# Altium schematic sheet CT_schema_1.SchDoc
size 470 x 459 mm
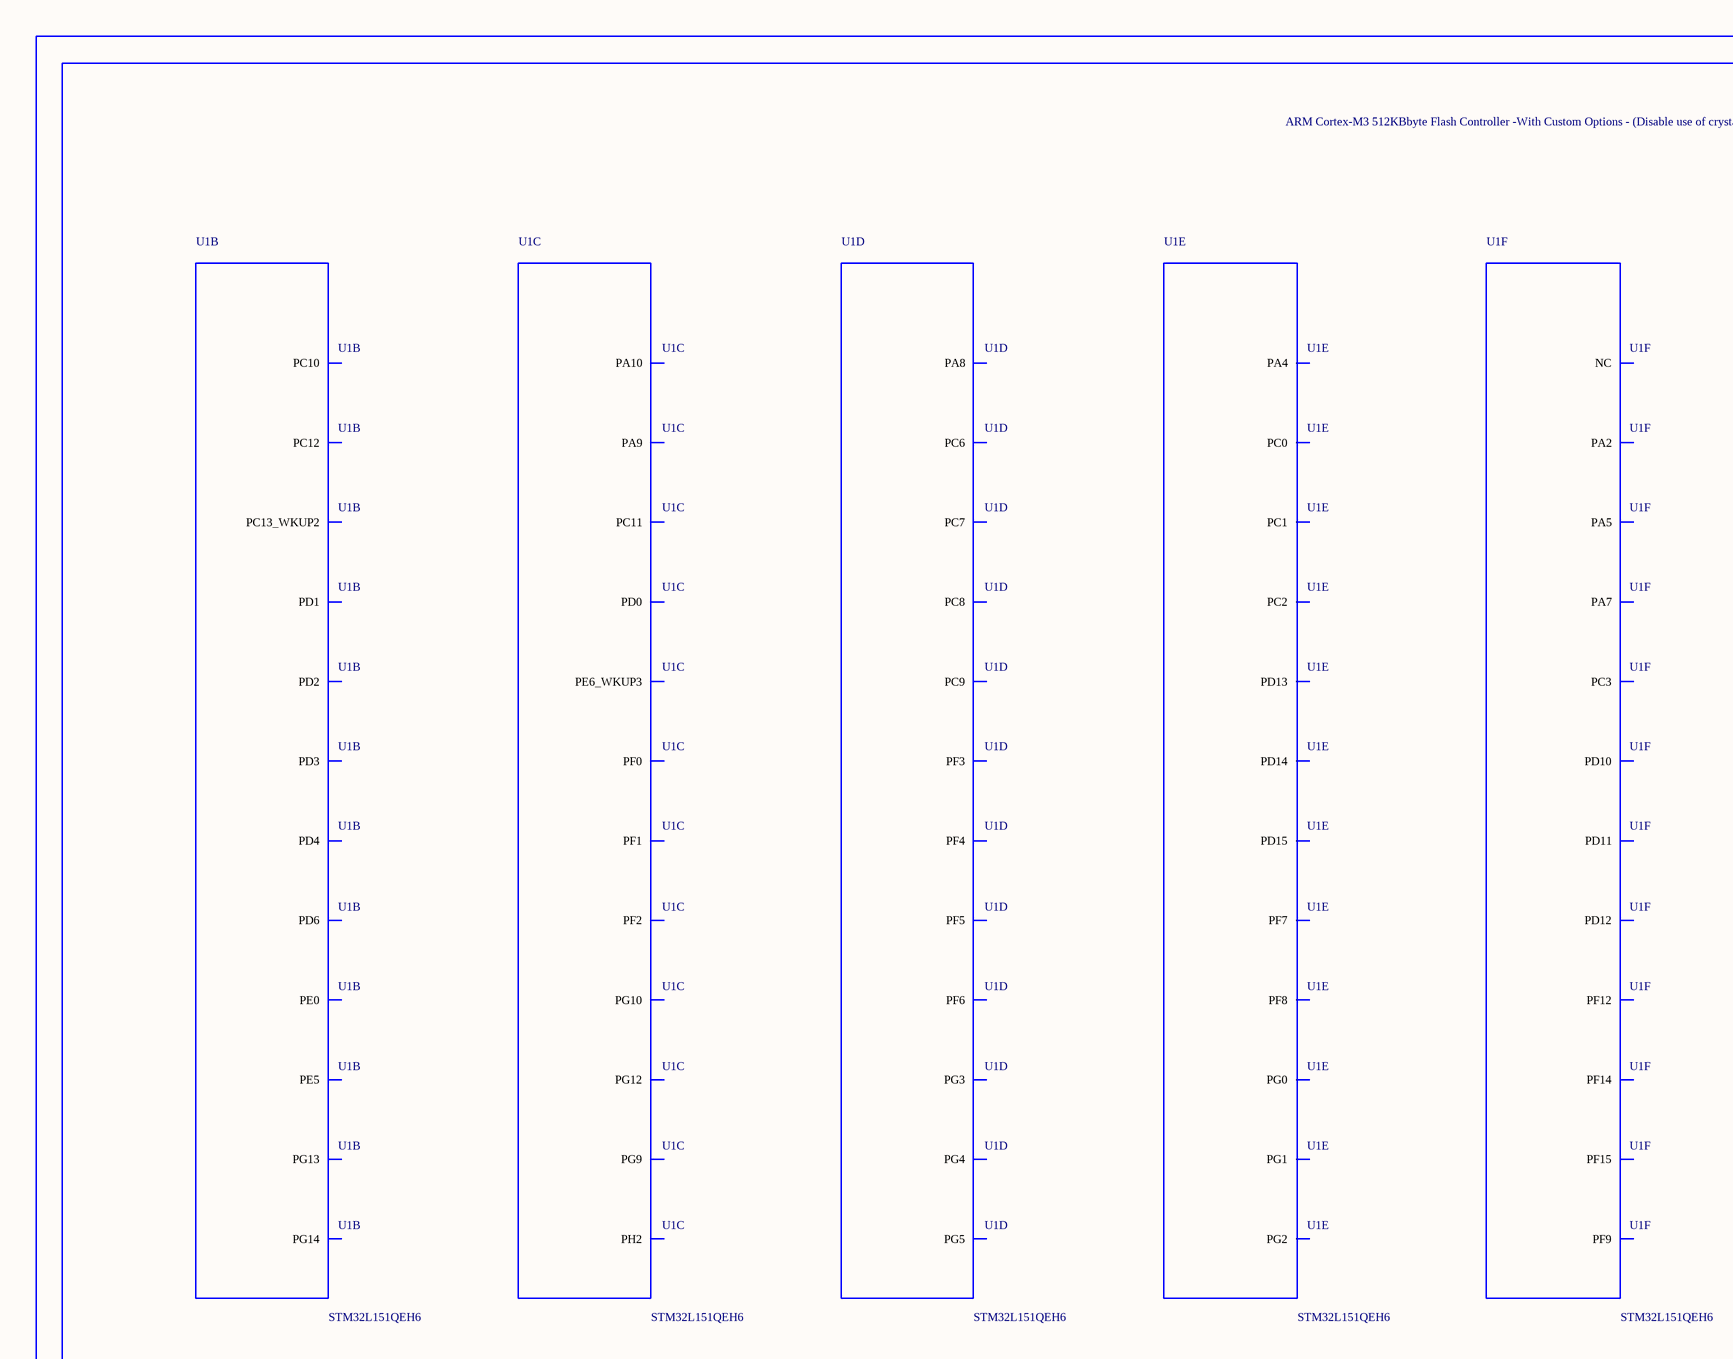
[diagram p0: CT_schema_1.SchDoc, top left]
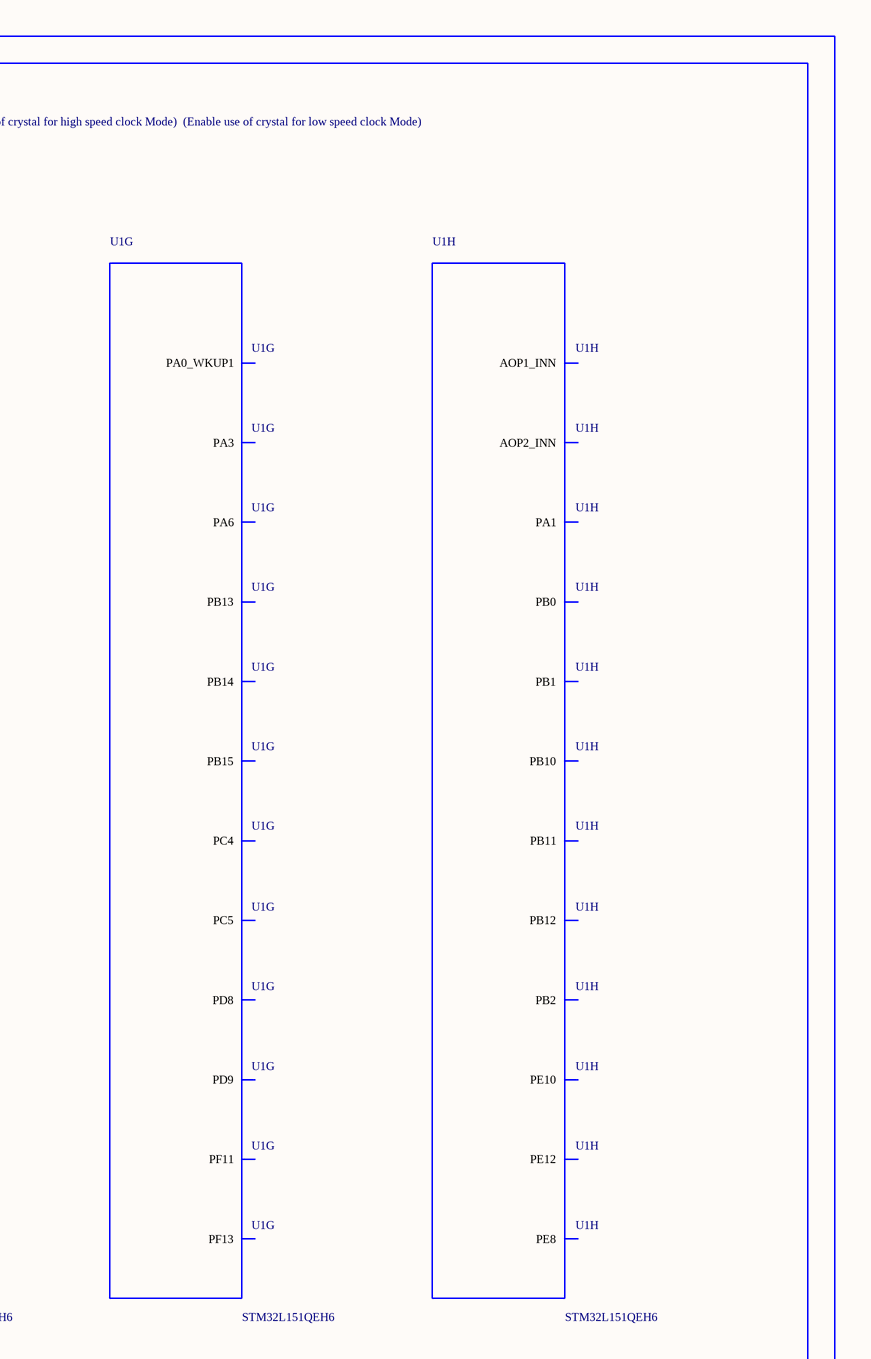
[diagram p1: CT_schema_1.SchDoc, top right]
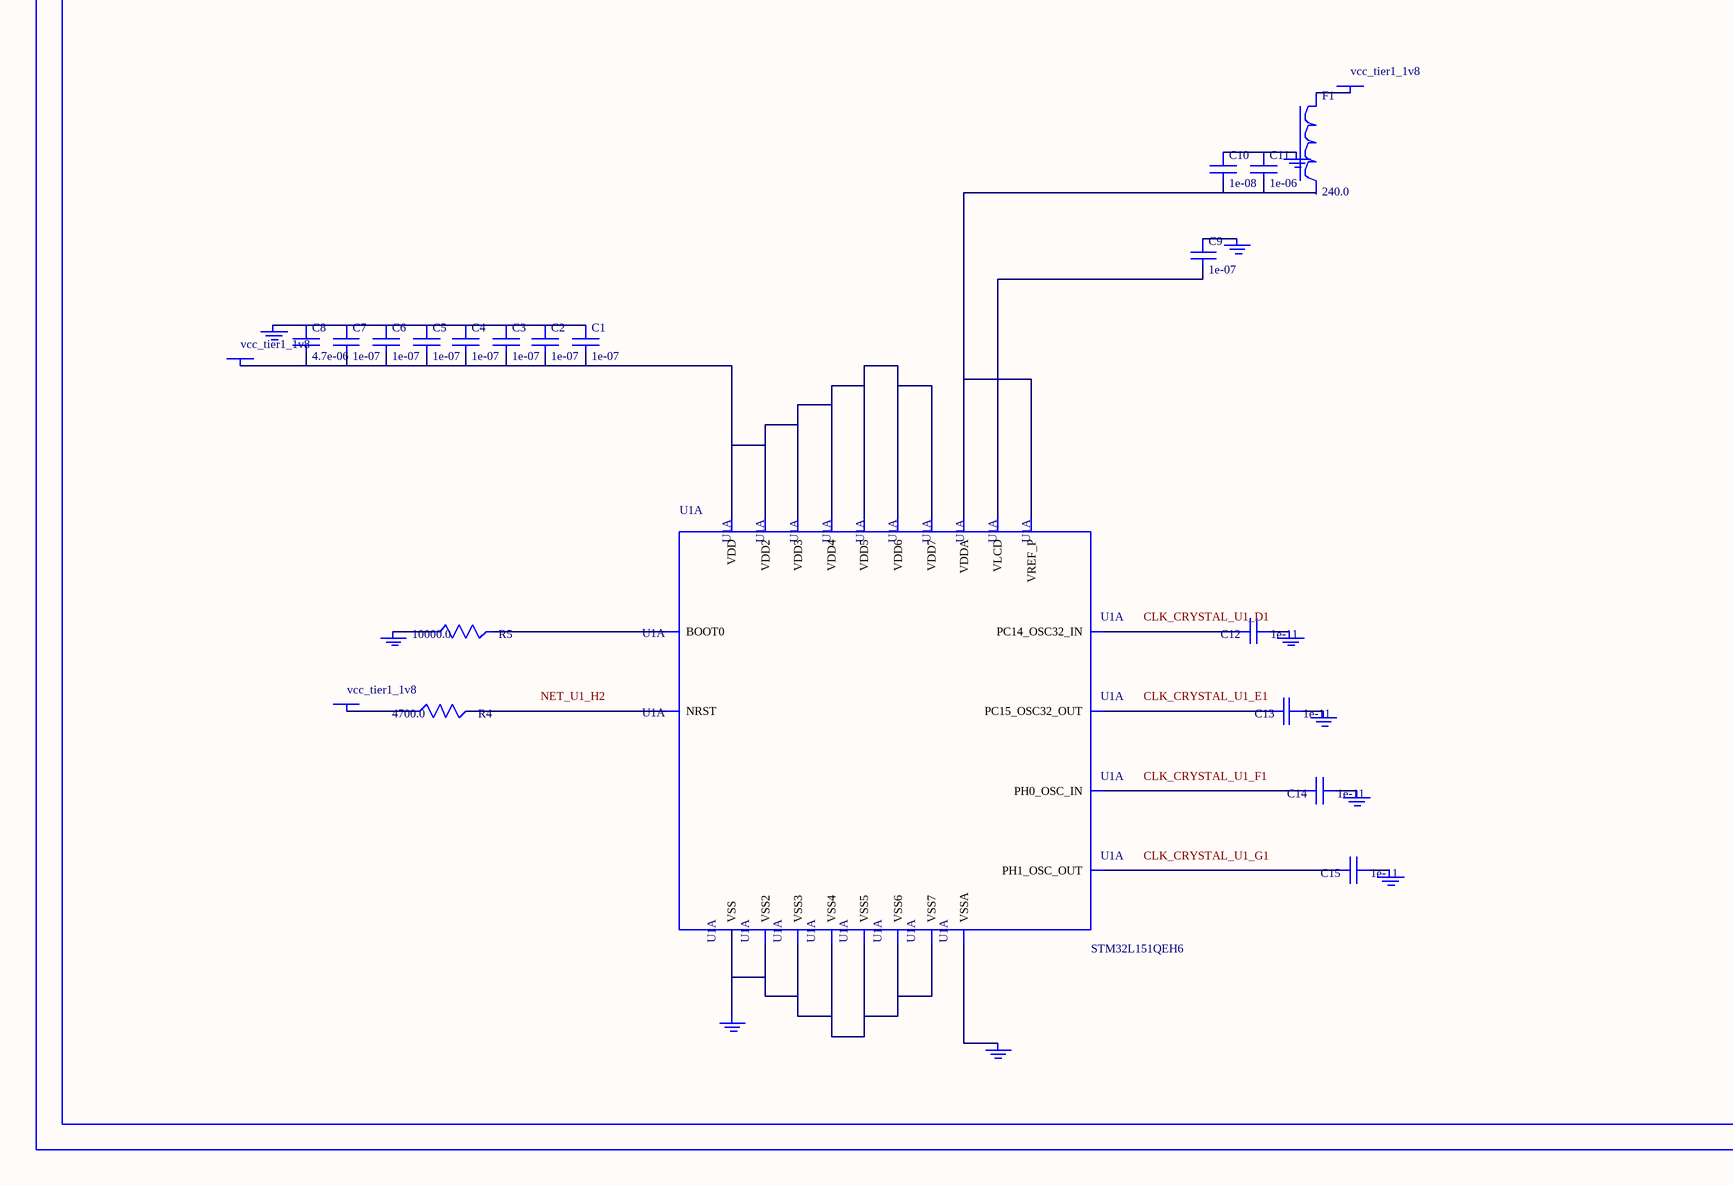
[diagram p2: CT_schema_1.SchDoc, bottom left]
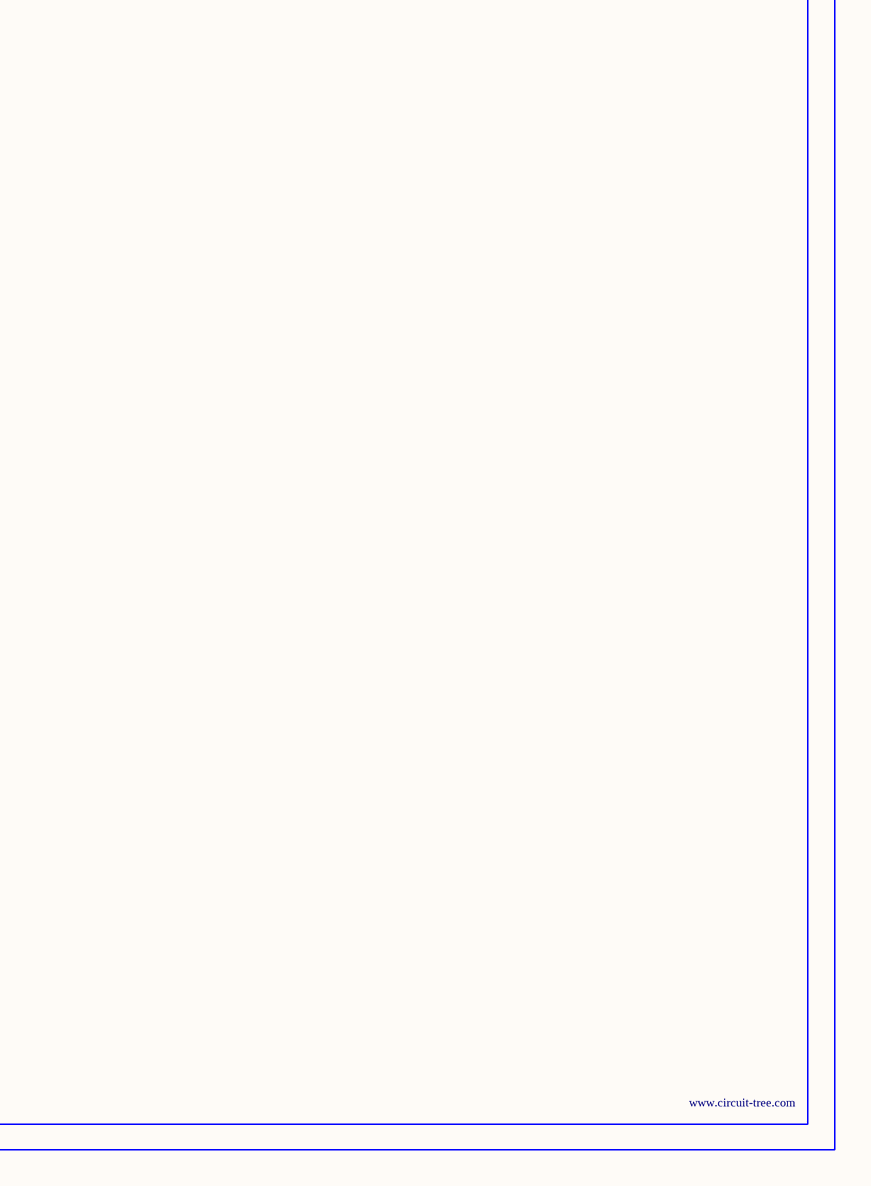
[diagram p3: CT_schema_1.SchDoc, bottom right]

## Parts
BORDER0  (no value)
C1  1e-07  [C0603]
C2  1e-07  [C0603]
C3  1e-07  [C0603]
C4  1e-07  [C0603]
C5  1e-07  [C0603]
C6  1e-07  [C0603]
C7  1e-07  [C0603]
C8  4.7e-06  [C0603]
C9  1e-07  [C0603]
C10  1e-08  [C0603]
C11  1e-06  [C0603]
C12  1e-11  [C0402]
C13  1e-11  [C0402]
C14  1e-11  [C0402]
C15  1e-11  [C0402]
F1  240.0  [L0603]
GND_INSTANCE_0_0  (no value)
GND_INSTANCE_0_1  (no value)
GND_INSTANCE_0_2  (no value)
GND_INSTANCE_0_3  (no value)
GND_INSTANCE_0_4  (no value)
GND_INSTANCE_0_5  (no value)
GND_INSTANCE_0_6  (no value)
GND_INSTANCE_0_7  (no value)
GND_INSTANCE_0_8  (no value)
GND_INSTANCE_0_9  (no value)
POWER_INSTANCE_0_0  vcc_tier1_1v8
POWER_INSTANCE_0_1  vcc_tier1_1v8
POWER_INSTANCE_0_2  vcc_tier1_1v8
R4  4700.0  [R0603]
R5  10000.0  [R0603]
U1  STM32L151QEH6  [UFBGA132]  (parts A,B,C,D,E,F,G,H of 11)

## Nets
NetC1_1: C1.1 C2.1 C3.1 C4.1 C5.1 C6.1 C7.1 C8.1 GND_INSTANCE_0_1.0(GND)
NetC1_2: C1.2 C2.2 C3.2 C4.2 C5.2 C6.2 C7.2 C8.2 POWER_INSTANCE_0_1.0(PWR) U1.C4(VDD) U1.G2(VDD4) U1.G6(VDD5) U1.G7(VDD6) U1.G11(VDD2) U1.G12(VDD3) U1.H3(VDD7)
NetC9_1: C9.1 GND_INSTANCE_0_2.0(GND)
NetC9_2: C9.2 U1.E2(VLCD)
NetC10_1: C10.1 C11.1 GND_INSTANCE_0_0.0(GND)
NetC10_2: C10.2 C11.2 U1.L1(VREF_P) U1.M1(VDDA)
NetC12_1: C12.1 GND_INSTANCE_0_4.0(GND)
NetC12_2: C12.2 U1.D1(PC14_OSC32_IN)
NetC13_1: C13.1 GND_INSTANCE_0_5.0(GND)
NetC13_2: C13.2 U1.E1(PC15_OSC32_OUT)
NetC14_1: C14.1 GND_INSTANCE_0_6.0(GND)
NetC14_2: C14.2 U1.F1(PH0_OSC_IN)
NetC15_1: C15.1 GND_INSTANCE_0_7.0(GND)
NetC15_2: C15.2 U1.G1(PH1_OSC_OUT)
NetF1_1: F1.1 POWER_INSTANCE_0_0.0(PWR)
NetGND_INSTANCE_0_3_0: GND_INSTANCE_0_3.0(GND) R5.1
NetGND_INSTANCE_0_8_0: GND_INSTANCE_0_8.0(GND) U1.J1(VSSA)
NetGND_INSTANCE_0_9_0: GND_INSTANCE_0_9.0(GND) U1.D3(VSS) U1.E3(VSS2) U1.F2(VSS5) U1.F6(VSS6) U1.F7(VSS7) U1.F11(VSS3) U1.F12(VSS4)
NetPOWER_INSTANCE_0_2_0: POWER_INSTANCE_0_2.0(PWR) R4.1
NetR4_2: R4.2 U1.H2(NRST)
NetR5_2: R5.2 U1.A4(BOOT0)

Not connected (* = marked no-connect by the designer): F1 2; U1 B6(PD6) B7(PD4) B8(PD3) B9(PD1) B10(PC12) B11(PC10) C1(PC13_WKUP2) C2(PE5) C3(PE0) C6(PG14) C7(PG13) C8(PD2) C9(PD0) C10(PC11) C11(PH2) C12(PA10) D2(PE6_WKUP3) D4(PF2) D5(PF1) D6(PF0) D7(PG12) D8(PG10) D9(PG9) D10(PA9) D11(PA8) D12(PC9) E4(PF3) E9(PG5) E10(PC8) E11(PC7) E12(PC6) F3(PF4) F4(PF5) F9(PG3) F10(PG4) G3(PF6) G4(PF7) G9(PG1) G10(PG2) H1(PC0) H4(PF8) H9(PG0) H10(PD15) H11(PD14) H12(PD13) J2(PC1) J3(PC2) J4(PA4) J5(PA7) J6(PF9) J7(PF12) J8(PF14) J9(PF15) J10(PD12) J11(PD11) J12(PD10) K1(NC) K2(PC3) K3(PA2) K4(PA5) K5(PC4) K6(PF11) K7(PF13) K8(PD9) K9(PD8) K10(PB15) K11(PB14) K12(PB13) L2(PA0_WKUP1) L3(PA3) L4(PA6) L5(PC5) L6(PB2) L7(PE8) L8(PE10) L9(PE12) L10(PB10) L11(PB11) L12(PB12) M2(PA1) M3(AOP1_INN) M4(AOP2_INN) M5(PB0) M6(PB1)

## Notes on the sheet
- Labels drawn without touching a wire or pin: CLK_CRYSTAL_U1_D1, CLK_CRYSTAL_U1_E1, CLK_CRYSTAL_U1_F1, CLK_CRYSTAL_U1_G1, NET_U1_H2

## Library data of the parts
BORDER0 = BORDER_PAGE0
C1-C7 C9 = 06035C104K4Z2A
C8 = GRM188R6YA475KE15D
C10 = 06035C103K4Z2A
C11 = C0603C105K3RACTU
C12-C15 = C0402C100K3GACTU
F1 = Z0603C241ASMST
GND_INSTANCE_0_0-GND_INSTANCE_0_9 = GND
POWER_INSTANCE_0_0-POWER_INSTANCE_0_2 = PWR
R4 = RC0603JR-074K7L
R5 = RC0603JR-0710KL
